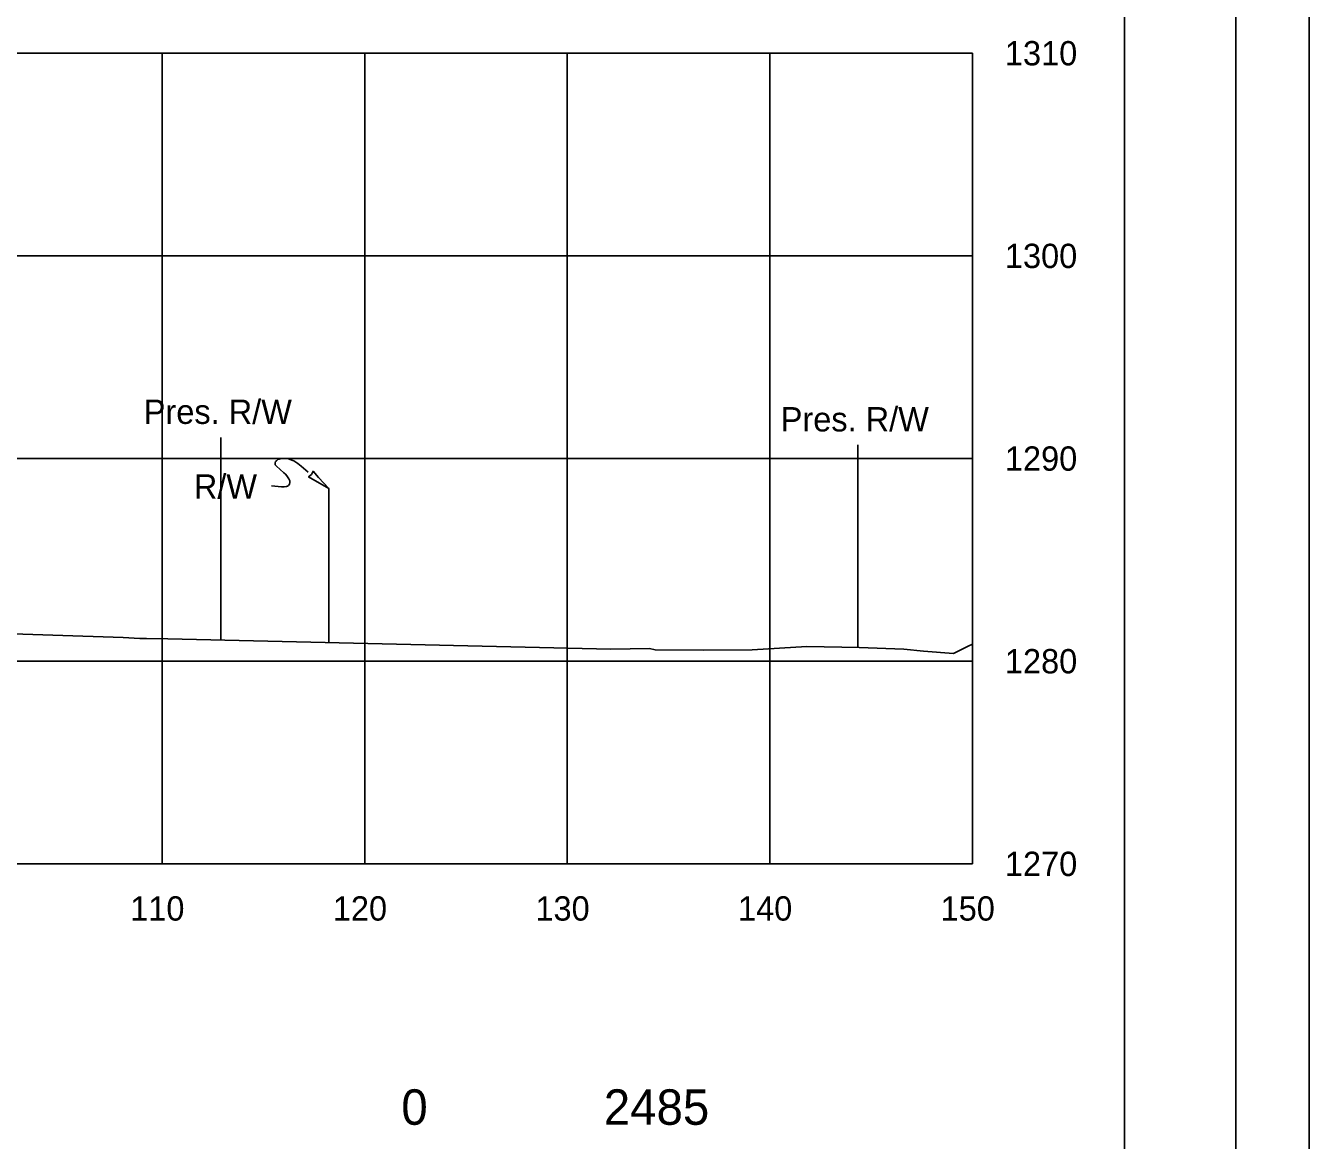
# Model space of a CAD drawing. Extents: x 2148105 to 2149976, y 144169 to 149705.
# Drawn here: x 2148516.6 to 2148579.9, y 145033.3 to 145088.3 of the extents above; entities that cross this region are included whole.
import ezdxf

# ---------------------------------------------------------------- set-up
doc = ezdxf.new("R2010")
doc.units = 0
for name, color, linetype in [('PH1a-PR-ServRd', 7, 'Continuous'), ('PR_Align_Ramp_A', 7, 'Continuous'), ('PR_Align_Ramp_E', 7, 'Continuous'), ('PR_Align_Ramp_J', 7, 'Continuous'), ('PR_Storm_Conc_Box_PH1B', 7, 'Continuous'), ('PR_Storm_Conc_Pipe_PH1B', 7, 'Continuous'), ('PR_Storm_Inlet_CICI_PH1B', 7, 'Continuous'), ('PR_Storm_MH_PH1A', 7, 'Continuous'), ('PR_Storm_MH_PH1B', 7, 'Continuous'), ('PR_Storm_Standard_Median_Drain_PH1B', 7, 'Continuous'), ('TOPO_BRIDGE_Low Beam', 7, 'Continuous')]:
    doc.layers.add(name, color=color, linetype=linetype)

msp = doc.modelspace()

# ---------------------------------------------------------------- linework, layer by layer
at = {"layer": 'PH1a-PR-ServRd'}
msp.add_lwpolyline([(2148570.822, 144921.906), (2148255.822, 144921.906), (2148255.822, 145131.906), (2148570.822, 145131.906)], close=True, dxfattribs=at)
at = {"layer": 'PR_Align_Ramp_E'}
msp.add_lwpolyline([(2148219.947, 145145.156), (2148579.947, 145145.156), (2148579.947, 144905.156), (2148219.947, 144905.156)], close=True, dxfattribs=at)
at = {"layer": 'PR_Align_Ramp_J'}
msp.add_lwpolyline([(2148236.322, 145136.906), (2148576.322, 145136.906), (2148576.322, 144916.906), (2148236.322, 144916.906)], close=True, dxfattribs=at)
at = {"layer": 'PR_Storm_Conc_Box_PH1B'}
for p, q in [((2148263.322, 145086.906), (2148563.322, 145086.906)), ((2148523.322, 145046.906), (2148523.322, 145086.906)), ((2148533.322, 145046.906), (2148533.322, 145086.906)), ((2148543.322, 145046.906), (2148543.322, 145086.906)), ((2148553.322, 145046.906), (2148553.322, 145086.906)), ((2148563.322, 145046.906), (2148563.322, 145086.906)), ((2148263.322, 145076.906), (2148563.322, 145076.906)), ((2148263.322, 145066.906), (2148563.322, 145066.906)), ((2148263.322, 145056.906), (2148563.322, 145056.906)), ((2148263.322, 145046.906), (2148563.322, 145046.906))]:
    msp.add_line(p, q, dxfattribs=at)
at = {"layer": 'PR_Storm_Conc_Pipe_PH1B'}
msp.add_lwpolyline([(2148255.822, 144921.906), (2148570.822, 144921.906), (2148570.822, 145131.906), (2148255.822, 145131.906)], close=True, dxfattribs=at)
msp.add_lwpolyline([(2148255.822, 144921.906), (2148570.822, 144921.906), (2148570.822, 145131.906), (2148255.822, 145131.906)], close=True, dxfattribs=at)
at = {"layer": 'PR_Storm_Inlet_CICI_PH1B'}
msp.add_lwpolyline([(2148514.443, 145058.311), (2148521.393, 145058.072), (2148522.221, 145058.031), (2148522.56, 145058.026), (2148523.602, 145058.008), (2148545.478, 145057.506), (2148547.375, 145057.527), (2148547.662, 145057.464), (2148550.047, 145057.446), (2148552.451, 145057.464), (2148555.142, 145057.626), (2148557.731, 145057.576), (2148559.935, 145057.498), (2148560.898, 145057.399), (2148562.379, 145057.281), (2148563.111, 145057.644), (2148563.322, 145057.743)], dxfattribs=at)
at = {"layer": 'PR_Storm_MH_PH1A'}
for p, q in [((2148526.219, 145057.948), (2148526.219, 145067.948)), ((2148557.658, 145057.577), (2148557.658, 145067.577))]:
    msp.add_line(p, q, dxfattribs=at)
at = {"layer": 'PR_Storm_Standard_Median_Drain_PH1B'}
for p, q in [((2148563.322, 145046.906), (2148563.322, 145086.906)), ((2148263.322, 145046.906), (2148563.322, 145046.906))]:
    msp.add_line(p, q, dxfattribs=at)
at = {"layer": 'TOPO_BRIDGE_Low Beam'}
msp.add_line((2148531.551, 145057.825), (2148531.551, 145065.425), dxfattribs=at)
for points in [[(2148530.54, 145066.236), (2148530.188, 145066.528), (2148530.026, 145066.656), (2148529.929, 145066.731), (2148529.829, 145066.786), (2148529.732, 145066.833), (2148529.615, 145066.871), (2148529.48, 145066.901), (2148529.387, 145066.91), (2148529.304, 145066.91), (2148529.22, 145066.903), (2148529.149, 145066.889), (2148529.097, 145066.875), (2148529.043, 145066.854), (2148529, 145066.827), (2148528.963, 145066.796), (2148528.927, 145066.753), (2148528.897, 145066.696), (2148528.9, 145066.638), (2148528.911, 145066.599), (2148528.965, 145066.53), (2148529.154, 145066.368), (2148529.339, 145066.204), (2148529.417, 145066.129), (2148529.48, 145066.054), (2148529.543, 145065.96), (2148529.58, 145065.898), (2148529.62, 145065.809), (2148529.626, 145065.732), (2148529.604, 145065.648), (2148529.562, 145065.579), (2148529.513, 145065.544), (2148529.456, 145065.521), (2148529.345, 145065.504), (2148529.212, 145065.512), (2148529.055, 145065.528), (2148528.72, 145065.564)], [(2148531.551, 145065.425), (2148531.035, 145065.975), (2148530.774, 145066.282), (2148530.692, 145066.114), (2148530.549, 145066), (2148531.551, 145065.425)]]:
    msp.add_lwpolyline(points, dxfattribs=at)

# ---------------------------------------------------------------- texts
at = {"layer": 'PR_Align_Ramp_A'}
for s, p in [('0', (2148535.131, 145034.031)), ('2485', (2148545.124, 145034.031))]:
    msp.add_text(s, height=1.75, dxfattribs=at).set_placement(p)
at = {"layer": 'PR_Storm_MH_PH1A'}
for p in [(2148522.419, 145068.615), (2148553.858, 145068.244)]:
    msp.add_text('Pres. R/W', height=1.2, rotation=360, dxfattribs=at).set_placement(p)
at = {"layer": 'PR_Storm_MH_PH1B'}
for s, p in [('1310', (2148564.922, 145086.306)), ('1300', (2148564.922, 145076.306)), ('1290', (2148564.922, 145066.306)), ('1280', (2148564.922, 145056.306)), ('1270', (2148564.922, 145046.306)), ('110', (2148521.749, 145044.106)), ('120', (2148531.749, 145044.106)), ('130', (2148541.749, 145044.106)), ('140', (2148551.749, 145044.106)), ('150', (2148561.749, 145044.106))]:
    msp.add_text(s, height=1.2, dxfattribs=at).set_placement(p)
at = {"layer": 'TOPO_BRIDGE_Low Beam'}
msp.add_text('R/W', height=1.2, rotation=360, dxfattribs=at).set_placement((2148524.889, 145064.928))

doc.saveas('drawing.dxf')
